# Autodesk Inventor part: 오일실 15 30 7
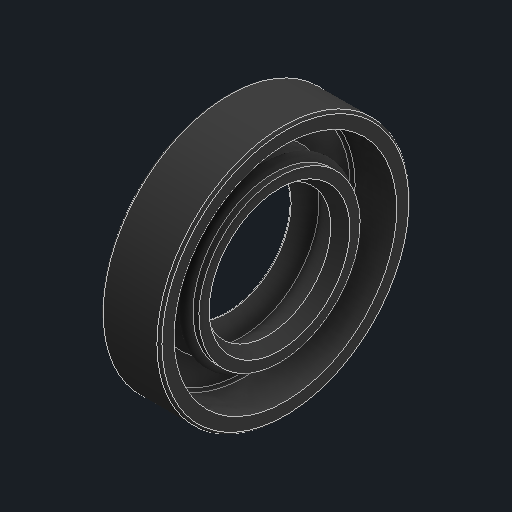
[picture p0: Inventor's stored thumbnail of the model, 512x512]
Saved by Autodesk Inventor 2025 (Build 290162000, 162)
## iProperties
Created: 2025-08
Part Number: 오일실 15 30 7
Material: 고무
Description: 오일-실
Document SubType Name: Modeling
Designer: infra10
Density: 0.93 g/cm^3
Appearance: 기본값
Author: jhkim
Sending System: Autodesk Inventor 2026
Preprocessor: ST-DEVELOPER v20.1
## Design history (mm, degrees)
feature "Solid1"
node "솔리드1"
